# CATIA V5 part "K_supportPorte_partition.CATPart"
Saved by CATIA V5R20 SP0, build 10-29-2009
Part number: support_porte_partition
Bounding box of the stored display mesh (mm): x -75.158 to -47.777, y -10 to -2, z -167.755 to 38.933
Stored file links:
  G:\Khaled_CFAO_2011\ST2M\ST2M_GR2\gcausse\Khaled\CAD_ThinkMotion\K_supportPorte_partition.CATPart
  C:\Documents and Settings\gcausse\Bureau\video thinkmotio\assemblage_gcausse\pupitre_think.CATProduct
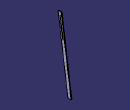
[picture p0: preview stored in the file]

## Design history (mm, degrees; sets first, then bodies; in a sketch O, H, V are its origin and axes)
Set1
  Sketch1 on Plane1, origin (-51.7528, 0, 6.3666), H (0, 1, 0), V (0.1221, 0, 0.9925)
    line L1 (-10, -175.4346) -> (-2, -175.4346)
    line L2 (-2, -175.4346) -> (-2, 32.5654)
    line L3 (-2, 32.5654) -> (-10, 32.5654)
    line L4 (-10, 32.5654) -> (-10, -175.4346)
    reference projected line E1 (-6, -35.4346) -> (-6, 24.5654) from Line1
    reference projected point E2 (-6, -35.4346) from Point1
    reference projected point E3 (-6, 24.5654) from Point2
    reference projected point E4 (-3, -170.4346) from Point3
    distance L4 L2 = 8
    distance L3 E3 = 8
    distance E4 L1 = 5
    parallelism: L2 L4, L4 E1
    equidistance: L4 L2 E2
Set2
  Plane1: linked copy from another document
  Line1: linked copy from another document
  Point1 to Point7: linked copy from another document
Body1 (main body)
  Pad1: profile Sketch1, direction (0.9925, 0, -0.1221), length -2
  Sketch2 on end face of Pad1, origin (-53.7378, 0, 6.6108), H (0, 1, 0), V (0.1221, 0, 0.9925)
    line L1 (-5.5, 24.5654) -> (-5.5, -35.4346)
    arc A1 centre (-6, -35.4346) radius 0.5 from (-5.5, -35.4346) to (-6.5, -35.4346) cw
    point P3 (-6, -35.4346)
    line L2 (-6.5, -35.4346) -> (-6.5, 24.5654)
    arc A2 centre (-6, 24.5654) radius 0.5 from (-6.5, 24.5654) to (-5.5, 24.5654) cw
    point P6 (-6, 24.5654)
    reference projected point E1 (-6, 24.5654) from Point2
    reference projected point E2 (-6, -35.4346) from Point1
    distance L2 L1 = 1
    vertical: L1 V
    tangency: A1 L1, L2 A1, A2 L1, A2 L2
    coincidence: P6 E1, P3 E2
  Pocket1: profile Sketch2, direction (0.9925, 0, -0.1221), length 2
  Sketch3 on end face of Pad1, origin (-50.219, -8.0022, 35.2147), H (0.1221, 0, 0.9925), V (0, 1, 0)
    point P1 (0.746, -0.9978)
    reference projected point E1 (0.746, -0.9978) from Point4
    coincidence: E1 P1
  Hole1: placed by Sketch3, at (-50.1279, -9, 35.955) direction (0.9925, 0, -0.1221), diameter 1, depth 1
  Sketch4 on end face of Pad1, origin (-50.1384, -3.8605, 35.87), H (0.1221, 0, 0.9925), V (0, 1, 0)
    point P1 (0.0857, 0.8605)
    reference projected point E1 (0.0857, 0.8605) from Point5
    coincidence: P1 E1
  Hole2: placed by Sketch4, at (-50.1279, -3, 35.955) direction (0.9925, 0, -0.1221), diameter 1, depth 1
  Sketch5 on end face of Pad1, origin (-74.6482, -3.4257, -163.3652), H (0.1221, 0, 0.9925), V (0, 1, 0)
    point P1 (0.8229, 0.4257)
    reference projected point E1 (0.8229, 0.4257) from Point6
    coincidence: P1 E1
  Hole3: placed by Sketch5, at (-74.5477, -3, -162.5485) direction (0.9925, 0, -0.1221), diameter 1, depth 1
  Sketch6 on end face of Pad1, origin (-74.5054, -7.9191, -162.2045), H (0.1221, 0, 0.9925), V (0, 1, 0)
    point P1 (-0.3467, -1.0809)
    reference projected point E1 (-0.3467, -1.0809) from Point7
    coincidence: P1 E1
  Hole4: placed by Sketch6, at (-74.5477, -9, -162.5485) direction (0.9925, 0, -0.1221), diameter 1, depth 1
